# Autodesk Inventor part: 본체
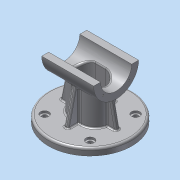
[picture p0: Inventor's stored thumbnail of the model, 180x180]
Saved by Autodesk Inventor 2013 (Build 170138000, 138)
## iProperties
Created: 2015-12
Part Number: 본체
Material: 알루미늄 6061
Document SubType Name: Modeling
Designer: mduedu
Density: 2.71 g/cm^3
Mass: 564.008 g
Surface Area: 536.242 cm^2
Volume: 208.121 cm^3
Author: mduedu
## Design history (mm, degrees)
sketch "스케치1"
  geometry: L1 (45, 40)-(-45, 40); L2 (-45, 40)-(-45, -40); L3 (-45, -40)-(45, -40); L4 (45, -40)-(45, 40); L5 (45, 40)-(-45, -40); L6 (-45, 40)-(45, -40); 2 further points
  constraints: 12 end point, 2 midpoint, 2 parallel, 1 coincident, 1 horizontal, 1 perpendicular, 3 other
  dimensions: "d0" = 90 distance of L2.end L3.end; "d2" = 80 distance of L1.end L2.end
extrude "돌출1" new body sketch "스케치1" distance "d3" = 10; taper "d4" = 0 deg
sketch "스케치2"
  geometry: C1 r 32.5 at (80, 0); 1 further point
  constraints: 1 centre point
  dimensions: "d5" = 65 diameter of C1; "d116" = 80 distance of point (0, 0) C1.centre
extrude "돌출2" join sketch "스케치2" stored distance "d7" = 75; taper "d8" = 0 deg
sketch "스케치3"
  geometry: L1 (-27.5, -20)-(27.5, -20); L2 (27.5, -20)-(27.5, 20); L3 (27.5, 20)-(-27.5, 20); L4 (-27.5, 20)-(-27.5, -20); L5 (-27.5, -20)-(27.5, 20); L6 (27.5, -20)-(-27.5, 20); 1 further point
  constraints: 12 end point, 2 midpoint, 2 parallel, 1 horizontal, 1 perpendicular
  dimensions: "d9" = 55 distance of L2.end L3.end; "d11" = 40 distance of L1.end L2.end
extrude "돌출3" new body sketch "스케치3" stored distance "d12" = 75; taper "d13" = 0 deg
fillet "모깎기1"
fillet "모깎기2"
feature "결합1"
  node "솔리드2"
sketch "스케치4"
  geometry: L1 (-37.5, 47.5)-(37.5, 47.5) reference; L2 (32.5, 47.5)-(40.208, 10); L3 (37.5, 47.5)-(37.5, 112.5) reference; L4 (60.208, 0)-(60.208, 10) reference; L5 (60.208, 10)-(-60.208, 10) reference; 1 further point
  constraints: 2 end point, 2 point on line
  dimensions: "d15" = 5 distance from line of L2.start L3; "d117" = 20 distance from line of L2.end L4
sketch "스케치5"
  geometry: L1 (10, 35.208)-(58.179, 24.085); L2 (0, 60.208)-(10, 60.208) reference; L3 (10, -60.208)-(10, 60.208) reference; 2 further points
  constraints: 2 end point, 1 point on line, 2 other
  dimensions: "d118" = 25 distance from line of L1.start L2; "d119" = 77 deg angle of L1 L3
feature "리브1" dims "d19" = 1, "d20" = 6, "d21" = 0, "d22" = 0, "d23" = 1, "d24" = 1
feature "리브2" dims "d25" = 1, "d26" = 6, "d27" = 0, "d28" = 0, "d29" = 1, "d30" = 1
fillet "모깎기4" dims "d31" = 2
fillet "모깎기5" dims "d32" = 2
fillet "모깎기16" dims "d149" = 2
sketch "스케치6"
  geometry: L1 (0, 0)-(-32.88, 32.88); L2 (0, 0)-(-46.5, 0); A1 r 46.5 centre (0, 0) between (-32.88, 32.88) and (-46.5, 0); 5 further points
  constraints: 4 end point, 2 coincident, 2 point on circle, 1 centre point, 1 horizontal, 5 other
  dimensions: "d120" = 93 diameter of A1; "d122" = 45 deg angle of L1 L2; "d126" = 360 deg dimension on point (0, 0) point (-32.88, 32.88) (derived)
hole "구멍1" sketch "스케치6" at (-32.88, 32.88), (-32.88, -32.88), (32.88, -32.88), (32.88, 32.88) diameter "d34" = 7; stored, may be unused: countersink angle "d38" = 90 deg, drill point angle "d40" = 118 deg; dims "d35" = 6, "d36" = 12, "d37" = 3, "d39" = 8
fillet "모깎기13" dims "d131" = 3
hole "구멍2" diameter "d44" = 45; stored, may be unused: countersink angle "d48" = 90 deg, drill point angle "d50" = 118 deg; dims "d42" = 10, "d43" = 10, "d45" = 6, "d46" = 4, "d47" = 2, "d49" = 8
sketch "스케치7" dims "d52" = 26.5
  geometry: L1 (0, 0)-(32.5, 0); L2 (0, 0)-(22.981, 22.981); A1 r 32.5 centre (0, 0) between (32.5, 0) and (22.981, 22.981) reference; 3 further points
  constraints: 4 end point, 2 point on circle, 1 coincident, 1 horizontal, 1 point on line, 3 other
  dimensions: "d51" = 45 deg angle of L2 L1
hole "구멍3" sketch "스케치7" at (18.738, 18.738) diameter "d54" = 2.459; stored, may be unused: countersink angle "d58" = 90 deg, drill point angle "d60" = 118 deg; dims "d55" = 8, "d56" = 4, "d57" = 2, "d59" = 10
sketch "스케치9"
  geometry: L1 (-75, 82.5)-(75, 82.5); L2 (75, 82.5)-(75, 0); L3 (75, 0)-(-75, 0); L4 (-75, 0)-(-75, 82.5); C1 r 32.5 at (0, 0) reference; 2 further points
  constraints: 8 end point, 2 parallel, 1 coincident, 1 horizontal, 1 midpoint, 1 perpendicular
  dimensions: "d71" = 50 distance edge to line of C1 L1; "d148" = 150 distance of L1.start L1.end
extrude "돌출5" cut sketch "스케치9" stored distance "d73" = 0; taper "d74" = 0 deg
node "작업 평면1"
sketch "스케치10"
  geometry: L1 (-7.5, 15)-(7.5, 15); L2 (-7.5, -15)-(7.5, -15); A1 r 15 centre (-7.5, 0) between (-7.5, 15) and (-7.5, -15); A2 r 15 centre (7.5, 0) between (7.5, -15) and (7.5, 15); A3 r 20 centre (-7.5, 0) between (-7.5, 20) and (-26.977, 4.545) reference; A4 r 20 centre (7.5, 0) between (26.977, 4.545) and (7.5, 20) reference; 1 further point
  constraints: 7 point on circle, 4 end point, 4 tangent, 3 point on line, 2 centre point, 2 horizontal, 1 concentric
  dimensions: "d150" = 5 radial gap between concentric circles of A1 A3; "d151" = 5 radial gap between concentric circles of A2 A4
extrude "돌출6" cut sketch "스케치10" stored distance "d78" = 50; taper "d79" = 0 deg
fillet "모깎기10" dims "d80" = 3
sketch "스케치11"
  geometry: 2 further points
  constraints: 1 coincident
hole "구멍4" sketch "스케치11" at (0, 0) diameter "d81" = 11; stored, may be unused: countersink angle "d85" = 90 deg, drill point angle "d87" = 118 deg; dims "d82" = 8, "d83" = 40, "d84" = 10, "d86" = 10
sketch "스케치12"
  geometry: C1 r 12 at (0, 0); 1 further point
  constraints: 1 centre point, 1 coincident
  dimensions: "d88" = 24 diameter of C1
extrude "돌출7" cut sketch "스케치12" distance "d89" = 5; taper "d90" = 0 deg
chamfer "모따기1" distance "d91" = 1; stored, may be unused: second distance "d92" = 2, angle "d93" = 45 deg
fillet "모깎기11" dims "d94" = 0.5
fillet "모깎기12" dims "d115" = 0.3
node "작업 평면3"
sketch "스케치17"
  geometry: 2 further points
  constraints: 1 horizontal alignment, 1 other
  dimensions: "d154" = 3.5 distance of point (-3.5, 0) point (0, 0)
feature "엠보싱1" sketch "스케치17" dims "d155" = 0.5, "d156" = 0
node "솔리드1"
mirror "대칭1"
mirror "대칭2"
pattern_circular "원형 패턴1" dims angle "d62" = 360 deg
mirror "대칭3"
